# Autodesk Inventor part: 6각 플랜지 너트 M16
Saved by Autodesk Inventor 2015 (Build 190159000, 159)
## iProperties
Created: 2026-07
Part Number: 6각 플랜지 너트 M16
Material: 일반
Document SubType Name: Modeling
Designer: user
Density: 1 g/cm^3
Appearance: 기본값
Author: user
Author: jhkim
Creation Date: 2026-07-01
Sending System: Autodesk Inventor 2027
Preprocessor: ST-DEVELOPER v20.1
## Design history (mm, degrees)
node "6각 플랜지 너트 M161"
body "Solid1"
node "기준1"
